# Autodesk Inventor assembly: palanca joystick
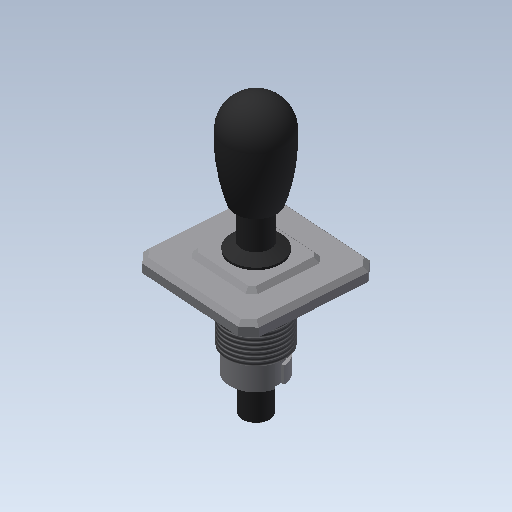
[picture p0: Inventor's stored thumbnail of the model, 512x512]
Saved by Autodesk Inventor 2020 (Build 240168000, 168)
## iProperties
Created: 2018-10
Part Number: palanca joystick
Document SubType Name: Assembly
Designer: Pedro
Author: Pedro
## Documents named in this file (6)
- C:\Users\Eresthor\Documents\Inventor\Pedro\joystick\palanca joystick.iam
- C:\Users\Eresthor\Documents\Inventor\Pedro\joystick\base palanca.ipt
- C:\Users\Eresthor\Documents\Inventor\Pedro\joystick\palanca.ipt
- C:\Users\Eresthor\Documents\Inventor\Pedro\joystick\muelle.ipt
- C:\Users\Eresthor\Documents\Inventor\Pedro\joystick\casquillo palanca.ipt
- C:\Users\Eresthor\Documents\Inventor\Pedro\joystick\arandela de seguridad.ipt
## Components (5 placed, 5 different names)
1. base palanca:1 — Coincidencia:1, Coincidencia:2, Coincidencia:6
2. palanca:1 — Coincidencia:1, Coincidencia:2, Coincidencia:4, Coincidencia:5, Nivelación:1
3. casquillo palanca:1 — Coincidencia:4, Nivelación:1, Coincidencia:7, Coincidencia:8
4. muelle:1 — Coincidencia:5, Coincidencia:6
5. arandela de seguridad:1 — Coincidencia:7, Coincidencia:8
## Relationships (8: Mate 7, Flush 1)
- Coincidencia:1 [Mate]: base palanca:1 ↔ palanca:1
- Coincidencia:2 [Mate]: base palanca:1 ↔ palanca:1
- Coincidencia:4 [Mate]: palanca:1 ↔ casquillo palanca:1
- Coincidencia:5 [Mate]: palanca:1 ↔ muelle:1
- Coincidencia:6 [Mate]: base palanca:1 ↔ muelle:1
- Nivelación:1 [Flush]: palanca:1 ↔ casquillo palanca:1
- Coincidencia:7 [Mate]: casquillo palanca:1 ↔ arandela de seguridad:1
- Coincidencia:8 [Mate]: casquillo palanca:1 ↔ arandela de seguridad:1
